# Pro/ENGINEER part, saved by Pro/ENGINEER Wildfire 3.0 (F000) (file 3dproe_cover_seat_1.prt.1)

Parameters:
  DESCRIPTION = "BRASS THRUST WASHER"
  MODELED_BY = "L. CONARD"
  PTC_COMMON_NAME = "BRASS THRUST WASHER"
